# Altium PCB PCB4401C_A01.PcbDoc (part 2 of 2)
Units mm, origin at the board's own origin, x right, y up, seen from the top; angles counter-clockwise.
Board outline 30 x 49 mm, 4 copper layers (Top Layer, Signal Layer 2, Signal Layer 3, Bottom Layer), stack 1.6 mm thick; 91 components, 90 nets, 342 pads, 490 vias.
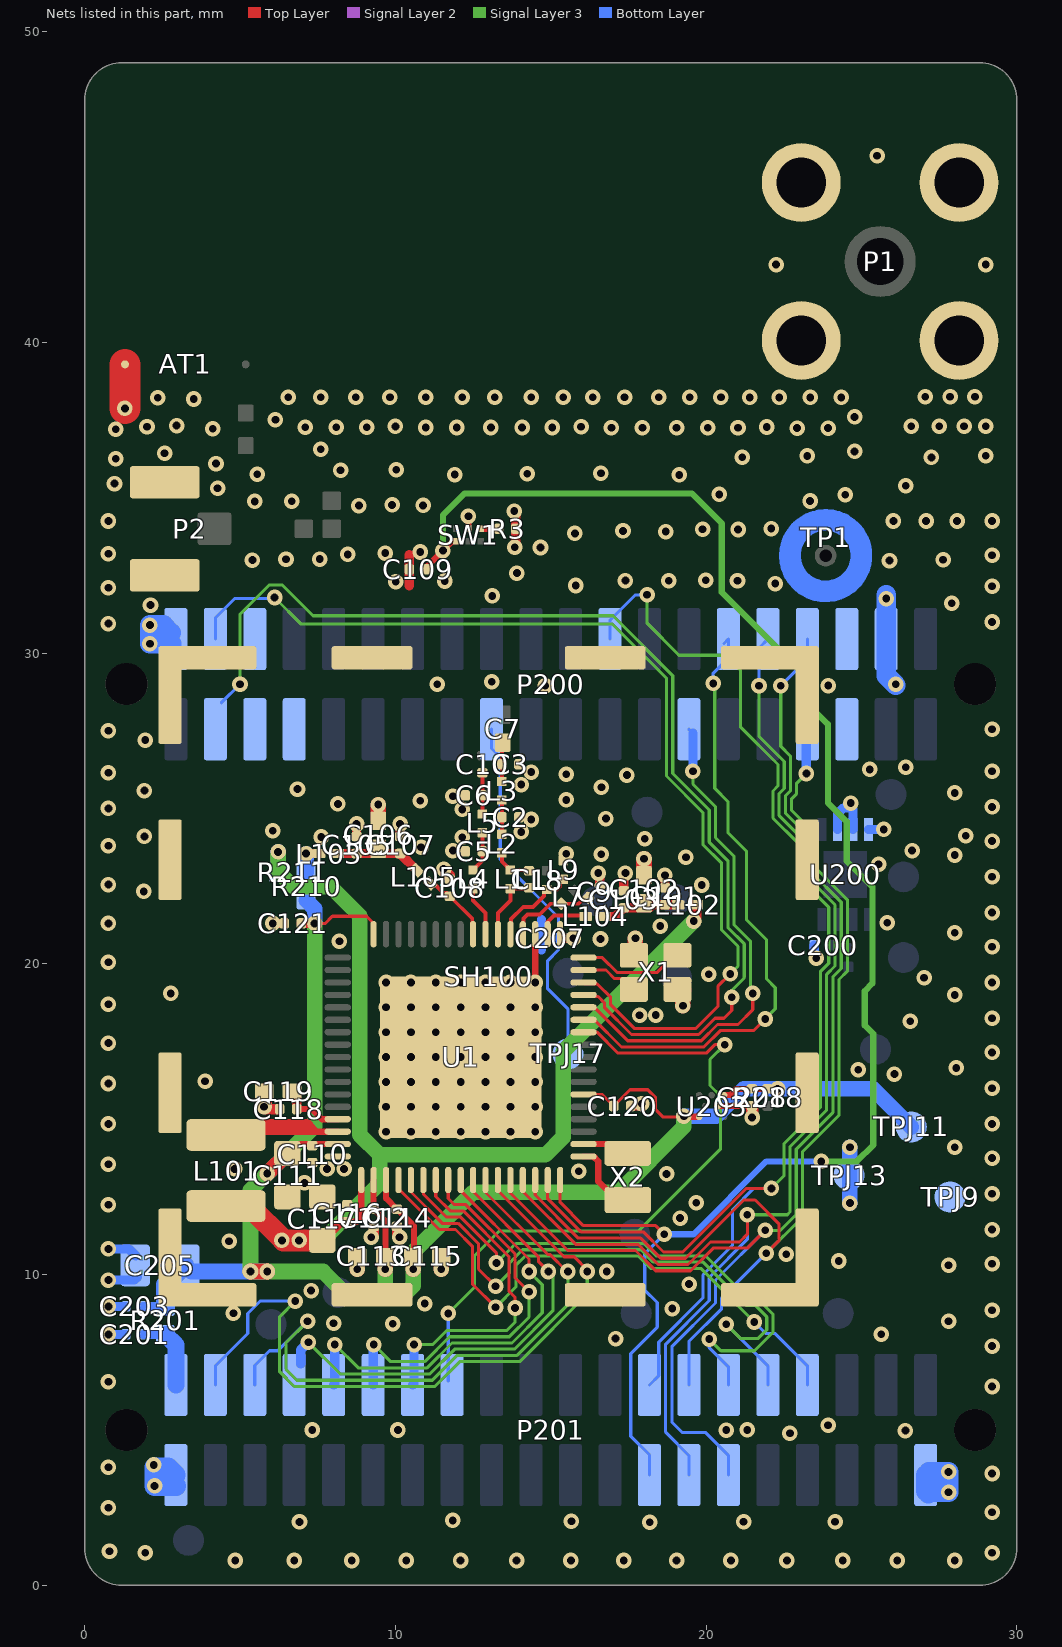
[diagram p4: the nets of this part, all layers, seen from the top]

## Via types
v1: diameter 0.5, hole 0.25, Top Layer to Bottom Layer, tented both sides, 490 vias

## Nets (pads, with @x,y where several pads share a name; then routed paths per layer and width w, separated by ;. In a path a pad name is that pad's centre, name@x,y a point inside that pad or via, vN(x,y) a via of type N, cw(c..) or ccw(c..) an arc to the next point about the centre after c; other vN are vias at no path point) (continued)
EFR32_PC7: P201.16 U1.11 | length 22.4
  Top Layer w0.1: U1.11@16.055,17.8 16.491,17.8 17.166,17.125 20.006,17.125 20.281,17.4 v1(20.6,17.4)
  Signal Layer 3 w0.1: v1(11.7,8.75) 12.55,9.6 12.55,10.617 13.333,11.4 17.819,11.4 20.464,14.046 20.464,15.746 20.125,16.085 20.125,16.925 v1(20.6,17.4)
  Bottom Layer w0.1: P201.16@11.7,6.575 v1(11.7,8.75)
EFR32_PC8: P200.30 U1.12 | length 20.2
  Top Layer w0.1: U1.12@16.055,18.2 16.4,18.2 17.275,17.325 19.924,17.325 20.449,17.85 21.525,17.85 v1(21.9,18.225)
  Signal Layer 3 w0.1: v1(20.225,29.025) 20.275,28.975 20.275,25.65 20.7,25.225 20.7,24.225 21.297,23.628 21.297,21.42 21.942,20.775 21.942,19.516 22.225,19.233 22.225,18.55 v1(21.9,18.225)
  Bottom Layer w0.1: v1(20.225,29.025) 20.225,29.35 20.715,29.84 P200.30@20.715,30.45 P200.30@20.575,30.31
EFR32_PC9: P200.27 U1.13 | length 16.2
  Top Layer w0.1: U1.13@16.035,18.6 16.4,18.6 17.475,17.525 19.841,17.525 20.366,18.05 21.025,18.05 21.5,18.525 v1(21.5,19.05)
  Signal Layer 3 w0.1: v1(19.575,26.2) 19.575,25.784 20.3,25.059 20.3,24.059 20.897,23.463 20.897,21.255 21.425,20.726 21.425,19.125 v1(21.5,19.05)
  Bottom Layer w0.1: P200.27@19.445,27.55 P200.27@19.575,27.42
  Bottom Layer w0.3: v1(19.575,26.2) P200.27@19.575,27.42
EFR32_PC10: P200.3 U1.14 | length 36.2
  Top Layer w0.1: U1.14@16.035,19 16.085,18.95 16.525,18.95 16.725,18.75 16.725,18.6 17.6,17.725 19.758,17.725 20.283,18.25 20.575,18.25 20.825,18.5 v1(20.825,18.925)
  Signal Layer 3 w0.1: v1(5,29) 5,31.25 5.938,32.188 6.362,32.188 7.35,31.2 17,31.2 18.925,29.275 18.925,26.125 20.1,24.95 20.1,23.916 20.697,23.319 20.697,21.172 21.225,20.644 21.225,19.579 21.224,19.578 21.224,19.544 20.825,19.145 v1(20.825,18.925)
  Bottom Layer w0.1: P200.3@4.4,28.4 v1(5,29)
EFR32_PC11: P200.4 U1.15 | length 33.7
  Top Layer w0.1: U1.15@16.035,19.4 16.085,19.35 16.5,19.35 16.925,18.925 16.925,18.683 17.683,17.925 19.675,17.925 20.375,18.625 20.375,19.275 v1(20.775,19.675)
  Signal Layer 3 w0.1: v1(6.114,31.788) 6.112,31.786 6.967,30.931 16.986,30.931 18.725,29.193 18.725,26.042 19.9,24.867 19.9,23.833 20.497,23.236 20.497,21.089 21.025,20.561 21.025,19.925 v1(20.775,19.675)
  Bottom Layer w0.1: P200.4@4.205,30.45 4.205,31.13 4.775,31.7 4.825,31.75 6.075,31.75 v1(6.114,31.788)
EFR32_PD0: U1.2 X2.1 | length 1.5
  Top Layer w0.2: U1.2@16.055,14.2 17.175,14.2 X2.1@17.475,13.9
EFR32_PD1: U1.1 X2.2 | length 2.4
  Top Layer w0.2: U1.1@16.055,13.8 16.375,13.8 16.525,13.65 16.525,13 17.125,12.4 X2.2@17.475,12.4
EFR32_PD2: C109.1 P201.25 SW1.4 U1.68 | length 55.5
  Top Layer w0.1: U1.68@15.3,13.045 15.3,12.325 16.05,11.575 18.375,11.575 v1(18.65,11.3)
  Top Layer w0.2: C109.1@11.002,32.771 v1(11.53,33.299) 11.831,33.6 SW1.4@11.95,33.6
  Signal Layer 3 w0.2: v1(11.53,33.299) 11.53,34.44 12.228,35.139 19.536,35.139 20.504,34.171 20.504,31.956 23.124,29.337 23.124,28.508 23.919,27.713 23.919,25.181 24.524,24.577 24.524,23.306 25.35,22.48 25.35,19.369 25.105,19.124 25.105,18.02 25.375,17.75 25.375,14.168 24.85,13.643 v1(23.702,13.643)
  Bottom Layer w0.1: P201.25@18.175,3.55 18.175,4.2 17.575,4.8 17.575,7.458 18.425,8.308 18.425,9.1 18.025,9.5 18.025,10.675 v1(18.65,11.3)
  Bottom Layer w0.2: v1(18.65,11.3) 19.596,11.3 21.939,13.643 v1(23.702,13.643)
EFR32_PD3: P200.24 P201.26 U1.67 | length 43.1
  Top Layer w0.1: U1.67@14.9,13.045 14.9,12.442 15.967,11.375 17.975,11.375 18.625,10.725 19.25,10.725 21.3,12.775 v1(22.1,12.775)
  Signal Layer 3 w0.1: v1(18.1,31.875) 18.1,30.958 19.127,29.931 20.627,29.931 21.1,29.458 21.1,27.625 22.311,26.414 22.311,25.726 22.15,25.564 22.15,24.687 22.942,23.894 22.942,22.82 23.946,21.817 23.946,20.014 23.676,19.744 23.676,15.378 22.499,14.201 22.499,13.174 v1(22.1,12.775)
  Bottom Layer w0.1: P200.24@16.905,30.45 16.905,31.055 17.725,31.875 v1(18.1,31.875) ; P201.26@18.175,6.45 18.475,6.75 18.475,7.825 19.9,9.25 19.9,9.991 20.85,10.941 20.85,12.091 21.534,12.775 v1(22.1,12.775)
EFR32_PD4: P200.33 P201.28 U1.66 | length 35.5
  Top Layer w0.1: U1.66@14.5,13.045 14.5,12.559 15.884,11.175 17.892,11.175 18.542,10.525 19.333,10.525 21.208,12.4 21.575,12.4 22.35,11.625 22.35,11.101 v1(21.937,10.688)
  Signal Layer 3 w0.1: v1(21.937,10.688) 23.099,11.85 23.099,13.953 24.276,15.13 24.276,19.496 24.546,19.766 24.546,22.065 23.542,23.069 23.542,24.143 22.75,24.935 22.75,25.316 22.911,25.477 22.911,25.811 v1(23.225,26.125)
  Bottom Layer w0.1: P201.28@19.445,6.45 19.445,7.845 20.5,8.9 20.5,9.251 v1(21.937,10.688) ; P200.33@23.225,27.52 P200.33@23.255,27.55
  Bottom Layer w0.3: v1(23.225,26.125) P200.33@23.225,27.52
EFR32_PD5: P200.32 P201.27 U1.65 | length 41.1
  Top Layer w0.1: U1.65@14.1,13.045 14.1,12.676 15.801,10.975 17.809,10.975 18.459,10.325 19.416,10.325 20.141,11.05 21.075,11.05 21.325,11.3 v1(21.325,11.925)
  Signal Layer 3 w0.1: v1(21.325,11.925) 22.608,11.925 22.699,12.016 22.699,14.118 23.876,15.295 23.876,19.662 24.146,19.932 24.146,21.9 23.142,22.903 23.142,23.977 22.35,24.77 22.35,25.481 22.511,25.643 22.511,26.514 21.7,27.325 v1(21.7,28.95)
  Bottom Layer w0.1: P201.27@19.445,3.55 19.445,4.18 18.695,4.93 18.695,7.762 20.1,9.167 20.1,9.908 21.325,11.133 v1(21.325,11.925) ; v1(21.7,28.95) 21.7,30.165 P200.32@21.985,30.45
EFR32_PD6: P200.34 P201.29 U1.64 | length 42.1
  Top Layer w0.1: U1.64@13.7,13.045 13.7,12.625 15.55,10.775 17.726,10.775 18.376,10.125 19.499,10.125 20.224,10.85 21.325,10.85 v1(21.9,11.425)
  Signal Layer 3 w0.1: v1(21.9,11.425) 22.391,11.425 22.899,11.933 22.899,14.036 24.076,15.212 24.076,19.579 24.346,19.849 24.346,21.983 23.342,22.986 23.342,24.06 22.55,24.853 22.55,25.399 22.711,25.56 22.711,26.689 22.4,27 v1(22.4,28.95)
  Bottom Layer w0.1: P201.29@20.715,3.55 20.715,4.185 19.975,4.925 19.225,4.925 18.895,5.255 18.895,7.679 20.3,9.084 20.3,9.825 v1(21.9,11.425) ; v1(22.4,28.95) 23.255,29.805 P200.34@23.255,30.45
EFR32_PD7: P201.4 U1.63 | length 23.3
  Top Layer w0.1: U1.63@13.3,13.045 13.3,12.7 15.425,10.575 15.75,10.575 16.175,10.15 v1(16.175,10.1)
  Signal Layer 3 w0.1: v1(6.775,9.15) 6.274,8.649 6.274,6.874 6.749,6.4 11.271,6.4 12.071,7.2 14,7.2 16.175,9.375 v1(16.175,10.1)
  Bottom Layer w0.1: P201.4@4.205,6.45 4.205,7.058 5.25,8.103 5.25,8.75 5.65,9.15 v1(6.775,9.15)
EFR32_PD8: P201.6 U1.62 | length 20.2
  Top Layer w0.1: U1.62@12.9,13.045 12.9,12.643 14.893,10.65 14.972,10.65 15.522,10.1 v1(15.55,10.1)
  Signal Layer 3 w0.1: v1(7.175,8.5) 6.474,7.799 6.474,6.957 6.831,6.6 11.188,6.6 11.988,7.4 13.917,7.4 15.55,9.033 v1(15.55,10.1)
  Bottom Layer w0.1: P201.6@5.475,6.45 5.475,7.075 5.95,7.55 6.217,7.55 7.167,8.5 v1(7.175,8.5)
EFR32_PD9: P201.8 U1.61 | length 15.3
  Top Layer w0.1: U1.61@12.5,13.045 12.5,12.675 14.6,10.575 14.6,10.425 v1(14.925,10.1) v1@14.925,10.225
  Signal Layer 3 w0.1: v1(7.2,7.825) 8.225,6.8 11.105,6.8 11.905,7.6 13.834,7.6 15.067,8.832 15.067,9.958 v1(14.925,10.1)
  Bottom Layer w0.3: P201.8@6.95,7.125 6.95,7.575 v1(7.2,7.825)
EFR32_PD10: P201.10 U1.60 | length 14.4
  Top Layer w0.1: U1.60@12.1,13.045 12.1,12.7 14.3,10.5 v1(14.3,10.1)
  Signal Layer 3 w0.1: v1(8.05,7.75) 8.8,7 11.023,7 11.823,7.8 13.751,7.8 14.725,8.774 14.725,9.675 v1(14.3,10.1)
  Bottom Layer w0.3: P201.10@8.015,6.45 8.05,6.485 v1(8.05,7.75)
EFR32_PD11: P201.12 U1.59 | length 12.8
  Top Layer w0.1: U1.59@11.7,13.045 11.7,12.45 11.9,12.25 12.267,12.25 13.85,10.667 13.85,9.9 v1(14.3,9.45)
  Signal Layer 3 w0.1: v1(9.3,7.75) 9.85,7.2 10.94,7.2 11.74,8 13.669,8 14.3,8.631 v1(14.3,9.45)
  Bottom Layer w0.3: P201.12@9.285,6.45 9.285,7.735 v1(9.3,7.75)
EFR32_PD12: P201.14 U1.58 | length 10.7
  Top Layer w0.1: U1.58@11.3,13.045 11.3,12.511 11.761,12.05 12.184,12.05 13.65,10.584 13.65,9.475 13.85,9.275 v1(13.85,8.925)
  Signal Layer 3 w0.1: v1(10.6,7.75) 11.207,7.75 11.657,8.2 13.586,8.2 13.85,8.464 v1(13.85,8.925)
  Bottom Layer w0.3: P201.14@10.555,6.45 10.6,6.495 v1(10.6,7.75)
EFR32_PD13: P201.30 U1.57 | length 18.9
  Top Layer w0.1: U1.57@10.9,13.045 10.9,12.594 11.644,11.85 12.101,11.85 13.25,10.701 v1(13.25,10.375)
  Signal Layer 3 w0.1: v1@13.25,10.225 v1(13.25,10.375) 13.875,11 17.984,11 18.384,10.6 19.991,10.6 21.391,9.2 21.674,9.2 22.15,8.724 22.15,8.142 21.558,7.55 20.475,7.55 v1(20.1,7.925)
  Bottom Layer w0.1: v1(20.1,7.925) 20.1,7.65 20.715,7.035 P201.30@20.715,6.45
EFR32_PD14: P201.32 U1.56 | length 19.7
  Top Layer w0.1: U1.56@10.5,13.045 10.5,12.656 11.506,11.65 12.019,11.65 12.675,10.994 12.675,10.175 v1(13.225,9.625)
  Signal Layer 3 w0.1: v1(13.225,9.625) 13.675,10.075 13.675,10.383 14.092,10.8 17.901,10.8 18.301,10.4 19.908,10.4 21.308,9 21.591,9 21.95,8.641 21.95,8.225 21.675,7.95 21.1,7.95 v1(20.65,8.4)
  Bottom Layer w0.1: v1(20.65,8.4) 21.985,7.065 P201.32@21.985,6.45
EFR32_PD15: P201.34 U1.55 | length 18.9
  Top Layer w0.1: U1.55@10.1,13.045 10.1,12.766 11.416,11.45 11.936,11.45 12.475,10.911 12.475,9.7 v1(13.225,8.95)
  Signal Layer 3 w0.1: v1(13.225,8.95) 13.875,9.6 13.875,10.3 14.175,10.6 17.819,10.6 18.219,10.2 19.825,10.2 v1(21.55,8.475)
  Bottom Layer w0.1: v1(21.55,8.475) 21.925,8.1 22.225,8.1 23.255,7.07 P201.34@23.255,6.45
EFR32_RESET: C207.1 P200.17 TPJ17.1 U1.18 | length 12.6
  Top Layer w0.3: U1.18@15.35,20.825 v1(15.725,20.825)
  Bottom Layer w0.1: P200.17@13.095,27.55 13.095,26.93 13.375,26.65 13.375,23.365 15.25,21.49 C207.1@15.25,20.95 ; C207.1@15.25,20.925 C207.1@15.25,20.825 15.25,20.45 14.9,20.1 14.9,19.2 15.55,18.55 TPJ17.1@15.55,17.1
  Bottom Layer w0.3: C207.1@15.25,20.825 v1(15.725,20.825)
GND: AT1.2 C2.2 C3.1 C5.2 C6.1 C9.1 C101.2 C102.2 C103.2 C105.2 C106.2 C107.2 C108.2 C109.2 C110.2 C111.2 C112.2 C113.2 C114.2 C115.2 C116.2 C117.2 C118.2 C119.2 C120.2 C121.2 C200.2 C201.2 C203.2 C205.2 C207.2 C208.2 L9.2 P1.2 P1.3 P1.4 P1.5 P2.2 P2.3 P200.2 P200.38 P201.1 P201.39 R3.2 SH100.1 SW1.2 TP1.2 TPJ13.1 U1.0 U1.20 U1.51 U200.2 U200.3 U200.4 U203.B2 X1.2 X1.4 | length 34
  Top Layer w0.2: SW1.2@12.35,34 v1(12.35,34.4) ; v1(14.5,19.4) U1.20@14.5,20.955 ; U203.B2@20.375,15.425 C208.2@21.475,15.425
  Top Layer w0.3: v1(6.05,21.3) C121.2@6.425,21.3 ; C105.2@8.75,24.1 v1(8.75,24.5) ; v1@8.8,24.45 v1@8.825,24.475 ; v1@10.075,24.5 v1@10.075,24.525 ; C107.2@10.15,24.1 v1(10.15,24.5) ; 10.449,32.171 C109.2@10.449,32.695 10.449,33.164 ; v1(13.825,34.568) 13.875,34.518 R3.2@13.875,34 13.875,33.439 v1(13.844,33.408) ; v1(16.526,22.921) 16.526,22.896 16.575,22.847 C9.1@16.575,22.545 ; C103.2@17.352,22.402 17.352,22.852 17.402,22.902 v1(17.402,22.919) ; C120.2@17.575,15.425 17.85,15.425 v1(17.925,15.5) ; C101.2@18.675,22.45 v1@18.675,22.8
  Top Layer w0.33: v1@9.3,11.225 C112.2@9.3,11.525 ; v1@10.05,11.225 C114.2@10.05,11.525
  Top Layer w0.34: v1(5.775,15.4) 5.775,15.325 C118.2@6.225,15.325 ; v1(11.55,23.05) 11.75,22.85 C108.2@11.75,22.75
  Top Layer w0.4: v1(21.478,15.055) C208.2@21.478,15.368
  Top Layer w0.5: v1(5.775,15.4) C119.2@5.775,15.9 ; v1(8.775,10.175) C113.2@8.775,10.525 ; C106.2@9.45,24.65 v1(9.45,25.125) ; v1(11.475,10.175) C115.2@11.475,10.5 ; X1.2@17.7,20.325 17.75,20.375 17.725,20.4 v1(17.725,20.825) ; C102.2@18,22.85 v1(18,23.378) ; X1.4@19.225,19.2 19.275,19.15 19.251,19.126 v1(19.251,18.651)
  Top Layer w1: v1(1.298,37.873) AT1.2@1.298,39.29
  Bottom Layer w0.3: v1(0.765,8.075) C201.2@1.325,8.075 ; v1(0.765,8.975) C203.2@1.325,8.975 ; v1(0.765,9.825) 1.6,9.825 C205.2@1.7,9.925 ; v1(0.765,10.825) 1.425,10.825 C205.2@1.65,10.6 ; 14.7,20.45 C207.2@14.7,20.825 14.7,21.425 ; C200.2@23.475,20.6 23.475,20.251 v1(23.546,20.18) ; U200.2@24.225,24.325 24.225,24.825 24.413,25.013 24.688,25.013 24.725,24.975 U200.3@24.725,24.325 ; U200.4@25.225,24.325 v1(25.714,24.325)
  Bottom Layer w0.5: v1(24.625,12.3) v1(24.625,14.1) ; P200.38@25.795,30.45 P200.38@25.8,30.455
  Bottom Layer w0.635: P200.2@2.785,30.65 2.535,30.9 v1(2.1,30.9) v1(2.1,30.3) P200.2@2.8,30.3 ; P201.1@2.9,3.25 2.95,3.2 v1(2.25,3.2) 2.25,3.8 2.685,3.8 P201.1@2.935,3.55 ; v1@25.795,31.868 v1(25.795,31.755) P200.38@25.795,30.45 25.795,29.274 v1@26.101,28.968 ; P201.39@27.065,3.55 27.165,3.65 v1(27.8,3.65) ; P201.39@27.065,3.55 27.065,3.035 27.15,2.95 27.2,3 v1(27.8,3) v1(27.8,3.65) ; P201.39@27.065,3.55 27.7,3.55 v1(27.8,3.65)
  other v1: 4.848,0.8 6.748,0.8 8.598,0.8 10.348,0.8 12.098,0.8 13.898,0.8 15.648,0.8 17.348,0.8 19.048,0.8 20.798,0.8 22.598,0.8 24.398,0.8 26.148,0.8 27.998,0.8 1.948,1.05 29.2,1.05 0.8,1.1 18.184,2.028 6.914,2.042 15.663,2.063 21.205,2.045 24.149,2.045 11.847,2.089 29.2,2.35 0.765,2.5 29.2,3.6 0.765,3.8 2.225,3.875 22.696,4.895 26.412,4.98 7.325,5 10.081,5 20.647,4.996 21.323,5.001 23.925,5.15 29.2,6.4 0.765,6.55 29.2,7.7 17.084,7.941 25.635,8.08 8.013,8.438 9.913,8.42 27.8,8.5 4.787,8.754 29.2,8.85 18.911,8.906 10.944,9.069 7.288,9.485 19.449,9.695 16.8,10.1 27.8,10.3 29.2,10.35 24.267,10.438 22.576,10.654 4.65,11.075 9.225,11.2 10.135,11.2 29.2,11.45 19.162,11.82 0.765,12.25 19.684,12.309 29.2,12.6 7.075,12.95 18.725,13.239 15.9,13.325 4.825,13.4 7.8,13.4 8.35,13.4 0.765,13.55 29.2,13.75 28,14.1 9.7,14.6 10.5,14.6 11.3,14.6 12.1,14.6 12.9,14.6 13.7,14.6 14.5,14.6 0.765,14.85 29.2,14.85 9.7,15.4 10.5,15.4 11.3,15.4 12.1,15.4 12.9,15.4 13.7,15.4 14.5,15.4 29.2,16 0.765,16.15 9.7,16.2 10.5,16.2 11.3,16.2 12.1,16.2 12.9,16.2 13.7,16.2 14.5,16.2 3.875,16.225 26.059,16.454 24.891,16.591 28.05,16.65 9.7,17 10.5,17 11.3,17 12.1,17 12.9,17 13.7,17 14.5,17 29.2,17.15 0.765,17.45 9.7,17.8 10.5,17.8 11.3,17.8 12.1,17.8 12.9,17.8 13.7,17.8 14.5,17.8 26.57,18.149 29.2,18.25 17.858,18.343 18.375,18.35 9.7,18.6 10.5,18.6 11.3,18.6 12.1,18.6 12.9,18.6 13.7,18.6 14.5,18.6 0.765,18.7 28,19 2.775,19.05 9.7,19.4 10.5,19.4 11.3,19.4 12.1,19.4 12.9,19.4 13.7,19.4 29.2,19.4 27.014,19.55 20.085,19.663 0.765,20.05 29.2,20.55 8.2,20.725 16.6,20.8 28,21 18.522,21.216 0.765,21.3 25.825,21.325 29.2,21.65 1.905,22.33 0.765,22.55 19.856,22.537 29.2,22.8 18.675,22.85 25.548,23.206 19.349,23.432 28,23.5 16.625,23.525 15.5,23.54 11.85,23.645 26.625,23.643 10.825,23.75 0.765,23.8 29.2,23.95 18.025,24.025 7.615,24.081 12.15,24.07 1.925,24.1 28.35,24.125 14.05,24.245 6.05,24.283 14.375,24.645 16.775,24.675 12.15,24.97 0.765,25 29.2,25.05 8.15,25.145 24.65,25.175 10.8,25.25 15.5,25.275 11.85,25.395 28,25.5 1.925,25.575 6.85,25.625 16.631,25.685 14.05,25.77 17.45,26.075 15.5,26.1 0.765,26.15 14.375,26.17 29.2,26.2 25.263,26.256 26.422,26.323 1.95,27.2 0.765,27.5 29.2,27.55 14.825,28.95 23.926,28.956 11.35,29 26.101,29 13.1,29.075 0.765,30.95 29.2,31 2.12,31.547 27.9,31.6 13.119,31.841 0.765,32.1 29.2,32.15 15.8,32.175 22.225,32.238 10.013,32.294 11.585,32.319 17.402,32.333 18.798,32.33 21.008,32.329 19.991,32.34 13.91,32.576 25.9,32.975 5.4,32.994 27.625,33 6.48,33.019 7.564,33.024 29.2,33.15 8.468,33.176 0.765,33.2 9.677,33.219 10.803,33.253 14.669,33.397 15.776,33.85 18.701,33.912 17.324,33.93 19.883,33.983 21.028,33.977 22.095,34.007 0.765,34.25 26.025,34.25 27.075,34.25 28.075,34.25 29.2,34.25 8.828,34.746 10.889,34.753 9.895,34.767 5.472,34.882 6.665,34.889 23.345,34.894 20.424,35.105 24.477,35.098 4.279,35.301 26.424,35.388 0.961,35.455 11.907,35.742 19.135,35.731 5.552,35.757 14.245,35.772 16.613,35.784 8.235,35.882 10.025,35.902 4.228,36.097 1,36.25 27.25,36.294 21.165,36.305 23.251,36.343 29,36.35 2.574,36.433 24.778,36.489 7.601,36.558 1,37.2 4.119,37.218 22.925,37.242 23.925,37.242 7.1,37.267 8.1,37.267 9.075,37.267 10.975,37.258 11.975,37.258 13.075,37.258 14.075,37.258 15.05,37.258 16.95,37.25 17.95,37.25 19.05,37.25 20.05,37.25 21.025,37.25 2.007,37.282 10,37.292 15.975,37.283 21.95,37.275 26.6,37.3 27.5,37.3 28.3,37.3 29,37.3 2.96,37.323 6.14,37.511 24.775,37.6 3.51,38.176 2.352,38.217 21.4,38.225 22.35,38.225 23.35,38.225 24.35,38.225 6.55,38.233 7.6,38.233 8.725,38.233 9.825,38.233 10.975,38.233 12.15,38.233 13.2,38.233 14.375,38.233 15.4,38.233 16.35,38.233 17.375,38.233 18.475,38.233 19.475,38.233 20.475,38.233 27.05,38.25 27.85,38.25 28.65,38.25 22.25,42.5 29,42.5 25.5,46
N17556723: C118.1 C119.1 U1.48 | length 2
  Top Layer w0.2: C118.1@6.825,15.325 7.311,15.325 7.636,15 U1.48@8.145,15
  Top Layer w0.3: C118.1@6.825,15.325 C119.1@6.825,15.9
N17556727: L101.1 U1.49 | length 4.3
  Top Layer w0.2: 7,14.6 7.475,14.6 ; 7.225,14.85 7.475,14.6 ; U1.49@8.145,14.6 7.475,14.6
  Top Layer w0.5: L101.1@4.525,14.318 4.957,14.75 7.125,14.75
N17715113: L8.1 L9.1 U1.22 | length 2.9
  Top Layer w0.125: U1.22@13.7,20.955 13.725,20.98 13.725,21.443 14.115,21.833 14.433,21.833 14.787,22.187 14.787,22.307 L8.1@14.875,22.395 15.2,22.395 15.3,22.495 15.3,22.645 L9.1@15.4,22.745
N17715117: C6.2 C10.2 L5.2 | length 1.3
  Top Layer w0.125: L5.2@12.8,24.82 C6.2@12.8,25.42 C10.2@12.8,26.145
N17715119: C5.1 L4.2 L5.1 | length 1.3
  Top Layer w0.125: L4.2@12.5,23.02 12.8,23.32 C5.1@12.8,23.62 L5.1@12.8,24.22
N17715147: C2.1 L2.2 L3.1 | length 1.1
  Top Layer w0.125: L2.2@13.425,24.17 C2.1@13.425,24.72 L3.1@13.425,25.27
N17715149: C9.2 L7.1 U1.21 | length 2.8
  Top Layer w0.125: U1.21@14.125,21.03 14.125,21.46 14.251,21.586 14.646,21.586 14.993,21.933 L7.1@15.338,21.933 15.888,21.933 16.081,22.126 C9.2@16.206,22.126
N17715153: C3.2 C7.1 L3.2 | length 1.3
  Top Layer w0.125: L3.2@13.425,25.87 C3.2@13.425,26.42 13.425,27.095 C7.1@13.45,27.12
N17715266: C101.1 C102.1 C103.1 L102.1 L104.1 | length 2.5
  Top Layer w0.3: L104.1@16.725,21.525 17.075,21.525 C103.1@17.35,21.8 18.168,21.8 18.267,21.899 18.674,21.899 C101.1@18.675,21.9 L102.1@19.1,21.9
N17715332: C108.1 L105.2 U1.25 | length 2.3
  Top Layer w0.125: L105.2@11.112,22.588 11.237,22.588 11.55,22.275 11.65,22.275 C108.1@11.75,22.175 12.475,21.45 U1.25@12.475,20.98
N17715336: L104.2 U1.19 | length 1.7
  Top Layer w0.125: U1.19@14.9,20.935 U1.19@14.9,20.955 14.9,21.35 15.1,21.55 16.05,21.55 L104.2@16.073,21.527
N17715433: C105.1 C106.1 C107.1 L103.1 L105.1 | length 2.8
  Top Layer w0.3: L103.1@8.15,23.55 C107.1@10.15,23.55 L105.1@10.688,23.012
N17715450: U1.16 X1.3 | length 1.9
  Top Layer w0.1: U1.16@16.035,19.8 16.775,19.8 17.05,19.525 17.292,19.525 17.325,19.525 X1.3@17.675,19.175
N17715456: U1.17 X1.1 | length 3.5
  Top Layer w0.1: U1.17@16.035,20.2 16.658,20.2 17.133,19.725 18.425,19.725 18.975,20.275 X1.1@19.075,20.275
N17715531: L4.1 U1.24 | length 1.6
  Top Layer w0.125: L4.1@12.5,22.42 12.5,22.039 12.9,21.639 U1.24@12.9,20.955
N17715549: C1.1 L1.1 U1.23 | length 2.2
  Top Layer w0.125: U1.23@13.3,20.955 13.3,21.639 13.7,22.039 L1.1@13.7,22.42 14.275,22.42 C1.1@14.3,22.445
N17715564: C1.2 L1.2 L2.1 | length 1.3
  Top Layer w0.125: L2.1@13.425,23.57 13.425,23.295 L1.2@13.7,23.02 14.275,23.02 C1.2@14.3,22.995
N17747373: R3.1 SW1.1 | length 0.6
  Top Layer w0.2: SW1.1@12.75,34 R3.1@13.325,34
PAVDD: L103.2 R210.1 R211.2 | length 1
  Top Layer w0.3: v1(7.125,23.55) L103.2@7.55,23.55
  Bottom Layer w0.5: R211.2@7.125,22.95 v1(7.125,23.55)
USB_VBUS: P200.35
USB_VREG: P200.36
VDCDC: C116.1 C117.1 L101.2 L102.2 R211.1 U1.52 | length 40.1
  Top Layer w0.2: C116.1@8.45,11.7 8.75,11.7 8.9,11.85 U1.52@8.9,13.045
  Top Layer w0.3: C117.1@7.65,11.1 8.25,11.7 C116.1@8.45,11.7 ; v1(19.6,21.375) 19.7,21.475 L102.2@19.7,21.9
  Top Layer w0.7: L101.2@4.55,12.207 5.293,12.207 6.4,11.1 C117.1@7.65,11.1
  Signal Layer 2 w0.5: v1(6.35,11.1) v1(6.9,11.1)
  Signal Layer 3 w0.5: v1(6.225,23.6) 6.225,22.975 6.725,22.475 7.925,22.475 8.85,21.55 8.85,14.5 9.5,13.85 ; v1(6.35,11.1) v1(6.9,11.1) 7.65,11.1 9.5,12.95 9.5,13.85 ; v1(19.6,21.375) 15.4,17.175 15.4,14.425 14.825,13.85 9.5,13.85
  Bottom Layer w0.5: R211.1@6.225,22.95 v1(6.225,23.6) ; v1(6.35,11.1) v1(6.9,11.1)
VMCU: C110.1 C111.1 C112.1 C113.1 C114.1 C115.1 C120.1 C121.1 C203.1 C205.1 C208.1 R201.2 R210.2 R218.2 TPJ11.1 U1.6 U1.33 U1.50 U1.53 U1.54 U203.A1 U203.E3 | length 63.8
  Top Layer w0.1: v1(7.4,21.3) 7.742,21.3 7.972,21.53 9.07,21.53 9.3,21.3 U1.33@9.3,20.955 U1.33@9.3,20.935 ; U1.6@16.055,15.8 16.65,15.8 C120.1@17.025,15.425 17.55,15.95 18.125,15.95 18.375,15.7 18.375,15.3 18.6,15.075 19.279,15.075 v1@19.282,15.078
  Top Layer w0.2: C111.1@6.525,13.9 6.825,14.2 U1.50@8.145,14.2 ; U1.53@9.3,13.045 C112.1@9.3,12.1 9.311,12.1 9.68,11.731 C113.1@9.68,10.6 ; U1.54@9.7,13.045 9.7,12.45 C114.1@10.05,12.1 10.061,12.1 10.6,11.561 10.6,10.625 C115.1@10.575,10.6 ; v1@19.282,15.078 U203.E3@19.771,15.078 ; U203.A1@20.575,15.775 20.775,15.775 20.975,15.975 C208.1@21.475,15.975 R218.2@21.975,15.975 v1(22.3,15.975) v1@22.325,15.975
  Top Layer w0.3: C121.1@6.975,21.3 v1(7.4,21.3)
  Top Layer w0.5: v1(5.338,10.1) v1(5.875,10.1) ; v1(5.875,13.25) C111.1@6.525,13.9 ; v1(9.675,10.175) 9.675,10.595 C113.1@9.68,10.6 ; v1(10.575,10.175) C115.1@10.575,10.6
  Signal Layer 2 w0.5: v1(5.338,10.1) v1(5.875,10.1)
  Signal Layer 3 w0.5: v1(7.4,21.3) 7.4,14.775 v1(5.875,13.25) 5.338,12.712 v1(5.338,10.1) v1(5.875,10.1) 7.675,10.1 8.4,9.375 9.675,9.375 ; v1(9.675,10.175) 9.675,9.375 ; v1(19.285,15.092) 19.285,14.76 17.175,12.65 12.5,12.65 10.575,10.725 v1(10.575,10.175) 10.575,9.65 10.3,9.375 9.675,9.375
  Bottom Layer w0.3: C203.1@1.875,8.975 R201.2@2.6,8.975
  Bottom Layer w0.5: C205.1@3.225,10.3 3.425,10.1 v1(5.338,10.1) v1(5.875,10.1) ; R210.2@7.125,22.05 7.4,21.775 v1(7.4,21.3) ; v1(19.285,15.092) 20.322,15.092 21.204,15.975 v1(22.3,15.975) 25.375,15.975 TPJ11.1@26.6,14.75
  Bottom Layer w0.6: R201.2@2.6,8.975 2.6,9.675 C205.1@3.225,10.3
VMCU_IN: C201.1 P201.2 R201.1 | length 2.5
  Bottom Layer w0.3: C201.1@1.875,8.075 R201.1@2.6,8.075
  Bottom Layer w0.55: R201.1@2.6,8.075 2.935,7.74 P201.2@2.935,6.45
VRF: TPJ9.1
WSTK_P38: P200.5
WSTK_P39: P200.6
WSTK_P40: P200.7
pads on no net: P200.M1 P200.M2 P201.40 P201.M1 P201.M2 TPJ18.1 TPJ19.1 TPJ20.1 U200.9 U203.C1

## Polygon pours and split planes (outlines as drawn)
GND on Signal Layer 2 "GND_L2" (solid, remove dead copper, pour order 48): 0,0 0,38.656 21.794,38.656 21.794,46.409 30.131,46.409 30,0
GND on Top Layer "GND_L1" (solid, remove dead copper, pour order 56): 0,0 0,38.656 21.794,38.656 21.794,46.409 30,46.409 30,0
GND on Signal Layer 3 "GND_L3" (solid, remove dead copper, pour order 52): 0,0 0,38.656 21.794,38.656 21.794,46.409 30,46.409 30,0
GND on Bottom Layer "GND_L4" (solid, remove dead copper, pour order 54): 0,0 0,38.699 21.794,38.699 21.794,46.409 30,46.409 30,0

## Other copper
Top Layer:
  pour cut-out: 23.05,33.125 ccw(c23.868,33.143) 23.85,32.325 ccw(c23.794,33.181) 24.65,33.125 ccw(c23.795,33.096) 23.85,33.95 ccw(c23.857,33.143)
  pour cut-out: 10.375,32.421 11.074,32.421 11.074,32.994 10.375,32.994
  pour cut-out: 8.347,10.8 8.347,10.253 8.425,10.175 11.8,10.175 11.903,10.278 11.903,10.8
  region net GND: 8.475,13.9 7.65,13.9 7.5,13.75 7.325,13.75 7.15,13.575 7.15,13.4 6.65,12.9 6.5,12.9 6.5,12.1 8.525,12.1 8.625,12.2 8.625,13.525 8.575,13.575 8.575,13.8
  pour cut-out: 17.538,21.225 17.95,21.225 18.35,20.825 19.613,20.825 19.775,20.663 19.775,18.575 19.45,18.25 19.075,18.25 18.725,18.6 16.85,18.6 16.85,20.537
  pour cut-out: 10.55,23.594 10.55,24.924 9.993,25.481 8.917,25.481 7.906,24.469 7.906,23.594
  pour cut-out: 19.1,21.75 19.1,23.062 18.429,23.733 17.376,23.733 16.907,23.264 16.35,23.264 16.35,21.75
  region net GND: 11.6,23.826 11.6,23.51 11.71,23.401 12.23,23.401 12.4,23.571 12.4,24.059 12.273,24.186 11.96,24.186
  pour cut-out: 12.3,26.723 11.817,26.723 10.975,25.881 10.975,22.584 12.3,22.584
  pour cut-out: 16.363,22.545 13.775,22.545 13.775,27.47 15.65,27.47 16.363,26.757
  region net GND: 14.625,24.464 14.625,24.645 14.38,24.889 13.995,24.889 13.825,24.719 13.825,24.231 13.952,24.104 14.265,24.104
  region net GND: 14.625,25.989 14.625,26.275 14.309,26.59 13.923,26.59 13.82,26.487 13.82,25.761 13.972,25.609 14.245,25.609
  region net GND: 11.6,25.214 11.6,25.53 11.71,25.639 12.23,25.639 12.4,25.469 12.4,24.981 12.273,24.854 11.96,24.854
  region net GND: 15.25,23.215 15.55,23.215 15.75,23.415 15.75,27.137 15.149,27.739 14.878,27.739 14.862,27.722 14.862,27.651 15.25,27.262
  pour cut-out: 13.875,34.325 11.425,34.325 11.425,33.65 13.875,33.65
Signal Layer 2:
  pour cut-out: 23.05,33.125 ccw(c23.868,33.143) 23.85,32.325 ccw(c23.794,33.181) 24.65,33.125 ccw(c23.795,33.096) 23.85,33.95 ccw(c23.857,33.143)
  pour cut-out: 3.658,34.975 1.375,34.975 1.375,32.973 3.658,32.973 3.658,33.45 4.75,33.45 4.75,34.542 3.658,34.542
Signal Layer 3:
  pour cut-out: 23.05,33.125 ccw(c23.868,33.143) 23.85,32.325 ccw(c23.794,33.181) 24.65,33.125 ccw(c23.795,33.096) 23.85,33.95 ccw(c23.857,33.143)
Bottom Layer:
  pour cut-out: 7.1,26.447 2.722,26.447 2.722,26.7 7.1,26.7
  pour cut-out: 24.345,2.447 25.802,2.447 25.802,2.7 24.345,2.7
  pour cut-out: 19.265,5.347 22.025,5.347 22.025,5.6 19.265,5.6
  pour cut-out: 11.645,2.447 20.852,2.447 20.852,2.7 11.645,2.7
  pour cut-out: 4.025,2.447 6.67,2.447 6.67,2.7 4.025,2.7
  pour cut-out: 23.342,31.552 19.4,31.552 19.4,31.298 23.342,31.298
  pour cut-out: 15.625,26.447 18.182,26.447 18.182,26.7 15.625,26.7
  pour cut-out: 14.185,29.347 15.642,29.347 15.642,29.6 14.185,29.6
  pour cut-out: 14.477,28.64 13.02,28.64 13.02,28.387 14.477,28.387
  pour cut-out: 11.806,28.663 9.307,28.663 9.307,28.409 11.806,28.409
  pour cut-out: 13.04,29.36 10.48,29.36 10.48,29.614 13.04,29.614
  pour cut-out: 5.478,29.347 4.022,29.347 4.022,29.6 5.478,29.6
  pour cut-out: 23.045,5.447 24.725,5.447 24.725,5.7 23.045,5.7
  pour cut-out: 19.411,25.985 20.86,25.985 20.86,26.238 19.411,26.238
  pour cut-out: 4.415,4.809 4.694,4.809 4.694,5.597 4.415,5.597

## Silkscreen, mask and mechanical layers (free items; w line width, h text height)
Top Overlay:
  text "EFR32xG28" at 1.045,45.777 h3.2
  text "2.4 GHz" at 1.117,44.124 h1.9
  text "868/915 MHz" at 10.905,43.987 h1.9
  text "20 dBm" at 10.937,42.411 h1.9
  text "10 dBm" at 1.165,42.398 h1.9
  text "QFN68" at 1.165,40.66 h1.9
Bottom Overlay:
  lines w0.15: 1.375,41.575 1.375,40.575 2.375,40.575 ; 1.375,45.575 1.375,46.575 2.375,46.575 ; 19.375,40.575 20.375,40.575 20.375,41.575 ; 19.375,46.575 20.375,46.575 20.375,45.575
  lines w0.152: 5.697,22.758 5.697,22.458 5.997,22.458 ; 5.697,23.158 5.697,23.458 5.997,23.458 ; 6.347,22.458 6.647,22.458 6.647,22.158 ; 6.647,21.808 6.647,21.508 6.947,21.508 ; 6.697,23.358 6.697,23.458 6.947,23.458 ; 7.347,21.508 7.647,21.508 7.647,21.808 ; 7.397,23.458 7.647,23.458 7.647,23.358 ; 7.647,22.458 7.647,22.758
  text "BOARD INFO" at 20.425,46.925 h1.6
  text "PAVDD / Config." at 8.747,23.53 h1.6
  text "VDCDC" at 5.539,22.636 h1.2
  text "VMCU" at 6.859,18.02 h1.2 r270
  text "PCB4401C Rev. A01" at 28,13.7 h1.52 r270
Top Solder:
  the board outline again, w0.8
Bottom Solder:
  the board outline again, w0.8
BOARD OUTLINE 1:
  the board outline again, w0.1
M11:
  the board outline again, w0.1
M12:
  the board outline again, w0.1
M15:
  lines w0.025: 69.971,-48.875 70.179,-48.875 ; 70.075,-48.979 70.075,-48.771
  lines w0.1: -0.5,0 0.5,0 ; 0,-0.5 0,0.5
M16:
  lines w0.1: -0.5,0 0.5,0 ; 0,-0.5 0,0.5
M26:
  lines w0.2: -122.4,-40.25 -120.775,-40.25 ; -122.4,6.425 -120.775,6.425 ; -122.4,53.1 -120.775,53.1 ; -67.75,-88.5 -67.75,-86.9 ; -67.75,99.8 -67.75,101.4 ; -14.725,-88.5 -14.725,-86.9 ; -14.725,99.8 -14.725,101.4 ; 38.3,-88.5 38.3,-86.9 ; 38.3,99.8 38.3,101.4 ; 91.325,-88.5 91.325,-86.9 ; 91.325,99.8 91.325,101.4 ; 144.35,-40.225 145.975,-40.225 ; 144.35,6.45 145.975,6.45 ; 144.35,53.125 145.975,53.125 ; 145.975,-88.5 -122.4,-88.5 -122.4,101.4 145.975,101.4 145.975,-88.475 ; -120.775,-86.9 144.35,-86.9 144.35,99.8 -120.775,99.8 -120.775,-86.9
  text "5" at -94.425,100.325 h0.5
  text "4" at -41.4,100.3 h0.5
  text "3" at 11.625,100.3 h0.5
  text "2" at 64.65,100.3 h0.5
  text "1" at 117.775,100.3 h0.5
  text "D" at 145.025,76.2 h0.5
  text "D" at -121.725,76.175 h0.5
  text "C" at 145.025,29.5 h0.5
  text "C" at -121.725,29.475 h0.5
  text "B" at 145.025,-17.175 h0.5
  text "B" at -121.725,-17.2 h0.5
  text "A" at 145.025,-63.825 h0.5
  text "A" at -121.725,-63.85 h0.5
  text "5" at -94.425,-87.975 h0.5
  text "4" at -41.4,-88 h0.5
  text "3" at 11.625,-88 h0.5
  text "2" at 64.65,-88 h0.5
  text "1" at 117.775,-88 h0.5
M27:
  drawing of 28 lines, arcs and shapes, not listed
  text "Board Title" at 74.75,-61.95 h2.5
  text "EFR32xG28 Radio Board" at 76.15,-67.5 h2.5
  text "Page Title" at 74.75,-71.675 h2.5
  text "Designed:" at 42.5,-75.425 h1.7
  text "Approved:" at 58.7,-75.425 h1.7
  text "Top Assembly" at 76.15,-75.575 h3.2
  text "SzL" at 44.025,-77.925 h2.2
  text "RGU" at 60.075,-77.925 h2.2
  text "Revision" at 132.65,-78.7 h1.7
  text "Document number" at 74.75,-78.975 h2.35
  text "Size" at 42.5,-80.175 h1.7
  text "BOM Doc. No:" at 47.425,-80.175 h1.7
  text "A01" at 132.925,-81.75 h2.7
  text "PCB4401C" at 76.15,-81.85 h3.2
  text "A4" at 43.075,-82.025 h2
  text "<>" at 48,-82.025 h2
  text "Design Created Date:" at 42.5,-84.375 h1.7
  text "Sheet Created Date:" at 74.175,-84.375 h1.7
  text "Sheet Modified Date:" at 102.6,-84.375 h1.7
  text "Sheet" at 132.65,-84.375 h1.7
  text "Monday, July 13, 2020" at 43.575,-86.325 h1.7
  text "Monday, July 13, 2020" at 75.3,-86.325 h1.7
  text "'.Print_Date'" at 103.725,-86.325 h1.7
  text "1" at 133.85,-86.325 h1.7
  text "of" at 136.975,-86.325 h1.7
  text "2" at 139.7,-86.325 h1.7
M28:
  lines w0.2: -122.4,-40.25 -120.775,-40.25 ; -122.4,6.425 -120.775,6.425 ; -122.4,53.1 -120.775,53.1 ; -67.75,-88.5 -67.75,-86.9 ; -67.75,99.8 -67.75,101.4 ; -14.725,-88.5 -14.725,-86.9 ; -14.725,99.8 -14.725,101.4 ; 38.3,-88.5 38.3,-86.9 ; 38.3,99.8 38.3,101.4 ; 91.325,-88.5 91.325,-86.9 ; 91.325,99.8 91.325,101.4 ; 144.35,-40.225 145.975,-40.225 ; 144.35,6.45 145.975,6.45 ; 144.35,53.125 145.975,53.125 ; 145.975,-88.5 -122.4,-88.5 -122.4,101.4 145.975,101.4 145.975,-88.475 ; -120.775,-86.9 144.35,-86.9 144.35,99.8 -120.775,99.8 -120.775,-86.9
  text "5" at -94.1,100.325 h0.5
  text "4" at -41.075,100.3 h0.5
  text "3" at 11.95,100.3 h0.5
  text "2" at 64.975,100.3 h0.5
  text "1" at 117.95,100.3 h0.5
  text "D" at 145.35,76.2 h0.5
  text "D" at -121.4,76.175 h0.5
  text "C" at 145.35,29.5 h0.5
  text "C" at -121.4,29.475 h0.5
  text "B" at 145.35,-17.175 h0.5
  text "B" at -121.4,-17.2 h0.5
  text "A" at 145.35,-63.825 h0.5
  text "A" at -121.4,-63.85 h0.5
  text "5" at -94.1,-87.975 h0.5
  text "4" at -41.075,-88 h0.5
  text "3" at 11.95,-88 h0.5
  text "2" at 64.975,-88 h0.5
  text "1" at 117.95,-88 h0.5
M29:
  drawing of 28 lines, arcs and shapes, not listed
  text "Board Title" at -51.175,-61.95 h2.5
  text "EFR32xG28 Radio Board" at -52.575,-67.5 h2.5
  text "Page Title" at -51.175,-71.675 h2.5
  text "Approved:" at -35.125,-75.425 h1.7
  text "Designed:" at -18.925,-75.425 h1.7
  text "Bottom Assembly" at -52.575,-75.575 h3.2
  text "RGU" at -36.5,-77.925 h2.2
  text "SzL" at -20.45,-77.925 h2.2
  text "Revision" at -109.075,-78.7 h1.7
  text "Document number" at -51.175,-78.975 h2.35
  text "BOM Doc. No:" at -23.85,-80.175 h1.7
  text "Size" at -18.925,-80.175 h1.7
  text "A01" at -109.339,-81.75 h2.7
  text "PCB4401C" at -52.575,-81.85 h3.2
  text "<>" at -24.425,-82.025 h2
  text "A4" at -19.5,-82.025 h2
  text "Sheet" at -109.075,-84.375 h1.7
  text "Sheet Modified Date:" at -79.025,-84.375 h1.7
  text "Sheet Created Date:" at -50.6,-84.375 h1.7
  text "Design Created Date:" at -18.925,-84.375 h1.7
  text "2" at -116.125,-86.325 h1.7
  text "of" at -113.4,-86.325 h1.7
  text "2" at -110.275,-86.325 h1.7
  text "'.Print_Date'" at -80.15,-86.325 h1.7
  text "Monday, July 13, 2020" at -51.725,-86.325 h1.7
  text "Monday, July 13, 2020" at -20,-86.325 h1.7
M30:
  lines w0.2: -126.75,-94.975 -126.75,105.5 156.75,105.5 156.75,-94.975 -126.75,-94.975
